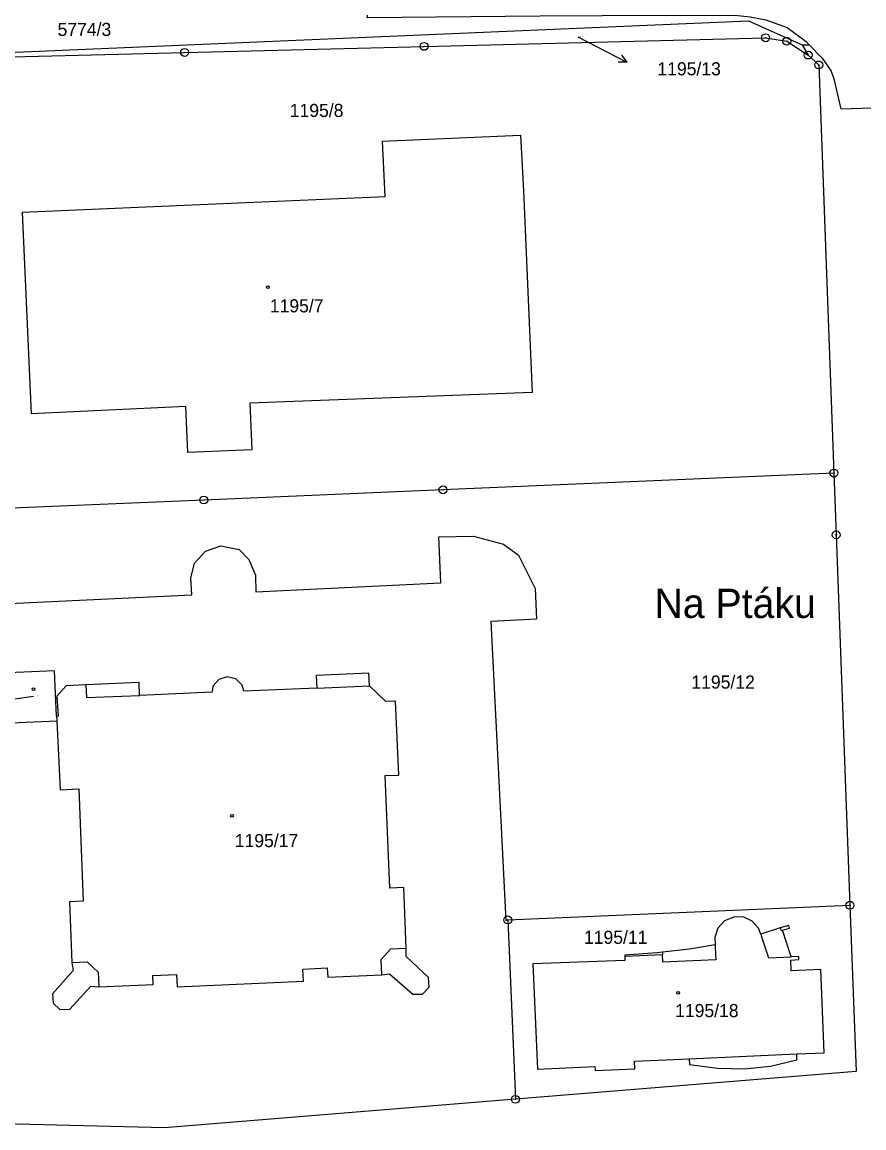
# Model space of a CAD drawing. Extents: x -737240 to -735272, y -1119606 to -1117878.
# Drawn here: x -736473.4 to -736364.4, y -1118998.9 to -1118855.7 of the extents above; entities that cross this region are included whole.
import ezdxf

# ---------------------------------------------------------------- set-up
doc = ezdxf.new("R2010")
doc.units = 0
for name, color, linetype in [('Level 1', 7, 'Continuous'), ('Level 15', 7, 'Continuous'), ('Level 16', 7, 'Continuous'), ('Level 18', 7, 'Continuous'), ('Level 19', 7, 'Continuous'), ('Level 25', 7, 'Continuous'), ('Level 4', 7, 'Continuous')]:
    doc.layers.add(name, color=color, linetype=linetype)

msp = doc.modelspace()

# ---------------------------------------------------------------- linework, layer by layer
at = {"layer": 'Level 1'}
for p, q in [((-736372.4, -1118858.66), (-736371.62, -1118860)), ((-736372.4, -1118858.66), (-736371.48, -1118858.67)), ((-736468.94, -1118945.6), (-736468.91, -1118946.19)), ((-736410.51, -1118971.99), (-736366.21, -1118970.09)), ((-736410.51, -1118971.99), (-736409.52, -1118995.22)), ((-736375.22, -1118973.03), (-736377.76, -1118973.84)), ((-736373.83, -1118976.76), (-736374.95, -1118973.32))]:
    msp.add_line(p, q, dxfattribs=at)
for points in [[(-736428.37, -1118853.26), (-736428.76, -1118855.15), (-736406.31, -1118854.93), (-736390.28, -1118854.83), (-736381.14, -1118854.83), (-736379.11, -1118855.04), (-736377.1, -1118855.44), (-736374.33, -1118856.44), (-736371.88, -1118858.26), (-736371.48, -1118858.67)], [(-736501.58, -1118860.78), (-736379.33, -1118855.55), (-736372.4, -1118858.66)], [(-736483.34, -1118860.44), (-736452.35, -1118859.66), (-736421.35, -1118858.88), (-736377.12, -1118857.76), (-736374.39, -1118858.2), (-736371.62, -1118860)], [(-736371.48, -1118858.67), (-736369.78, -1118860.4), (-736368.64, -1118862.08), (-736368.28, -1118863.06), (-736367.4, -1118866.97), (-736362.05, -1118866.78)], [(-736371.62, -1118860), (-736370.24, -1118861.28), (-736368.28, -1118914.13)], [(-736408.48, -1118877.58), (-736407.34, -1118903.68), (-736443.89, -1118905.09), (-736443.66, -1118911.11), (-736451.92, -1118911.45), (-736452.21, -1118905.49), (-736472.18, -1118906.46), (-736473.34, -1118880.33), (-736426.37, -1118878.32), (-736426.74, -1118871.15), (-736408.87, -1118870.39), (-736408.48, -1118877.58)], [(-736368.28, -1118914.13), (-736418.9, -1118916.3), (-736449.87, -1118917.62), (-736480.84, -1118918.95)], [(-736368.28, -1118914.13), (-736367.99, -1118922.13), (-736366.21, -1118970.09)], [(-736477.79, -1118931.14), (-736451.44, -1118929.89), (-736451.57, -1118927.72), (-736451.08, -1118925.8), (-736449.65, -1118924.23), (-736447.65, -1118923.56), (-736445.3, -1118924.04), (-736444.02, -1118925.33), (-736443.19, -1118927.35), (-736443.13, -1118929.51), (-736419.18, -1118928.35), (-736419.44, -1118922.39), (-736414.95, -1118922.31), (-736411.07, -1118923.33), (-736409.14, -1118924.78), (-736406.97, -1118929.07), (-736406.77, -1118933.06), (-736412.71, -1118933.36), (-736410.76, -1118972.06), (-736410.51, -1118971.99)], [(-736468.94, -1118945.6), (-736469.2, -1118939.73), (-736475.14, -1118939.98), (-736474.84, -1118946.46), (-736468.91, -1118946.19)], [(-736435.24, -1118941.96), (-736444.7, -1118942.35), (-736444.9, -1118941.61), (-736445.72, -1118940.78), (-736446.85, -1118940.5), (-736447.94, -1118940.84), (-736448.7, -1118941.72), (-736448.78, -1118942.52), (-736458.18, -1118942.91)], [(-736428.42, -1118941.68), (-736428.5, -1118940.04), (-736435.31, -1118940.32), (-736435.24, -1118941.96)], [(-736465.14, -1118941.56), (-736467.68, -1118941.7), (-736468.92, -1118943), (-736468.75, -1118945.59), (-736468.94, -1118945.6)], [(-736458.18, -1118942.91), (-736458.25, -1118941.26), (-736465.14, -1118941.56)], [(-736423.65, -1118975.66), (-736423.98, -1118967.79), (-736425.77, -1118967.86), (-736426.4, -1118953.31), (-736424.61, -1118953.23), (-736425.03, -1118943.66), (-736426.3, -1118943.71), (-736428.42, -1118941.68)], [(-736468.91, -1118946.19), (-736468.46, -1118955.14), (-736466.06, -1118955.02), (-736465.5, -1118969.56), (-736467.27, -1118969.64), (-736466.94, -1118977.51)], [(-736366.21, -1118970.09), (-736365.41, -1118991.64), (-736409.52, -1118995.22)], [(-736377.76, -1118973.84), (-736378.04, -1118973.04), (-736378.85, -1118972.15), (-736379.93, -1118971.64), (-736381.12, -1118971.57), (-736382.44, -1118972.09), (-736383.3, -1118973.05), (-736383.69, -1118974.27), (-736383.66, -1118975.2)], [(-736374.95, -1118973.32), (-736374.04, -1118973.04), (-736374.13, -1118972.72), (-736375.22, -1118973.03)], [(-736383.66, -1118975.2), (-736387, -1118975.76), (-736390.49, -1118976.17)], [(-736426.82, -1118979.1), (-736425.82, -1118978.96), (-736422.81, -1118981.62), (-736421.54, -1118981.59), (-736420.71, -1118980.7), (-736420.76, -1118979.43), (-736423.67, -1118976.72), (-736423.65, -1118975.66)], [(-736395.36, -1118976.68), (-736395.34, -1118977.23), (-736407.26, -1118977.68), (-736406.68, -1118991.31), (-736399.22, -1118990.99), (-736399.2, -1118991.49), (-736394.07, -1118991.27), (-736394.11, -1118990.27), (-736387.02, -1118989.96)], [(-736390.49, -1118976.17), (-736391.16, -1118976.25), (-736395.36, -1118976.54), (-736395.36, -1118976.68)], [(-736373.1, -1118989.35), (-736369.53, -1118989.19), (-736369.99, -1118978.4), (-736373.8, -1118978.57), (-736373.86, -1118977.21), (-736372.82, -1118977.13), (-736372.83, -1118976.72), (-736373.83, -1118976.76)], [(-736466.94, -1118977.51), (-736466.77, -1118978.52), (-736469.46, -1118981.55), (-736469.38, -1118982.79), (-736468.53, -1118983.61), (-736467.22, -1118983.55), (-736464.52, -1118980.57), (-736463.47, -1118980.67)], [(-736463.47, -1118980.67), (-736456.43, -1118980.37), (-736456.48, -1118979.18), (-736453.39, -1118979.07), (-736453.31, -1118980.66), (-736436.96, -1118979.93), (-736437.03, -1118978.35), (-736433.88, -1118978.2), (-736433.83, -1118979.4), (-736426.82, -1118979.1)], [(-736387.02, -1118989.96), (-736386.98, -1118990.71), (-736383.37, -1118991.2), (-736379.92, -1118991.29), (-736376.48, -1118990.92), (-736373.07, -1118990.1), (-736373.1, -1118989.35)], [(-736409.52, -1118995.22), (-736454.98, -1118998.92), (-736479.39, -1118998.3)]]:
    msp.add_lwpolyline(points, dxfattribs=at)
at = {"layer": 'Level 16'}
for points in [[(-736401.44, -1118857.64), (-736397.77, -1118859.55), (-736395.108, -1118860.934)], [(-736395.765, -1118860.029), (-736395.108, -1118860.934), (-736396.226, -1118860.916)], [(-736471.93, -1118943.04), (-736474.66, -1118943.45), (-736477.627, -1118943.892)]]:
    msp.add_lwpolyline(points, dxfattribs=at)
at = {"layer": 'Level 25'}
for centre, major_axis in [((-736377.12, -1118857.76), (0.516, 0)), ((-736377.12, -1118857.76), (0.0375, 0)), ((-736374.39, -1118858.2), (0.516, 0)), ((-736452.35, -1118859.66), (0.516, 0)), ((-736421.35, -1118858.88), (0.516, 0)), ((-736421.35, -1118858.88), (0.0375, 0)), ((-736374.39, -1118858.2), (0.0375, 0)), ((-736371.62, -1118860), (0.516, 0)), ((-736452.35, -1118859.66), (0.0375, 0)), ((-736371.62, -1118860), (0.0375, 0)), ((-736370.24, -1118861.28), (0.516, 0)), ((-736370.24, -1118861.28), (0.0375, 0)), ((-736441.57, -1118890.07), (0.18, 0)), ((-736368.28, -1118914.13), (0.516, 0)), ((-736368.28, -1118914.13), (0.0375, 0)), ((-736418.9, -1118916.3), (0.516, 0)), ((-736418.9, -1118916.3), (0.0375, 0)), ((-736449.87, -1118917.62), (0.516, 0)), ((-736449.87, -1118917.62), (0.0375, 0)), ((-736367.99, -1118922.13), (0.516, 0)), ((-736367.99, -1118922.13), (0.0375, 0)), ((-736471.93, -1118942.11), (0.18, 0)), ((-736446.22, -1118958.52), (0.18, 0)), ((-736366.21, -1118970.09), (0.516, 0)), ((-736366.21, -1118970.09), (0.0375, 0)), ((-736410.51, -1118971.99), (0.516, 0)), ((-736410.51, -1118971.99), (0.0375, 0)), ((-736388.45, -1118981.42), (0.18, 0)), ((-736409.52, -1118995.22), (0.516, 0)), ((-736409.52, -1118995.22), (0.0375, 0))]:
    msp.add_ellipse(centre, major_axis=major_axis, ratio=0.9848078, dxfattribs=at)
at = {"layer": 'Level 4'}
for p, q in [((-736435.24, -1118941.96), (-736428.42, -1118941.68)), ((-736395.36, -1118976.68), (-736390.48, -1118976.47)), ((-736390.49, -1118976.17), (-736390.48, -1118976.47)), ((-736387.02, -1118989.96), (-736373.1, -1118989.35))]:
    msp.add_line(p, q, dxfattribs=at)
for points in [[(-736465.14, -1118941.56), (-736465.07, -1118943.2), (-736458.18, -1118942.91)], [(-736377.76, -1118973.84), (-736377.6, -1118974.29), (-736376.75, -1118976.88), (-736373.83, -1118976.76)], [(-736375.22, -1118973.03), (-736375.13, -1118973.38), (-736374.95, -1118973.32)], [(-736383.66, -1118975.2), (-736383.65, -1118975.56), (-736383.56, -1118977.14), (-736390.45, -1118977.47), (-736390.48, -1118976.47)], [(-736426.82, -1118979.1), (-736426.9, -1118977.11), (-736425.67, -1118975.75), (-736423.65, -1118975.66)], [(-736466.94, -1118977.51), (-736464.99, -1118977.43), (-736463.55, -1118978.75), (-736463.47, -1118980.67)]]:
    msp.add_lwpolyline(points, dxfattribs=at)

# ---------------------------------------------------------------- texts
at = {"layer": 'Level 15'}
msp.add_text('Na Ptáku', height=3.8, dxfattribs=at).set_placement((-736391.52, -1118932.9))
at = {"layer": 'Level 16'}
msp.add_text('1195/13', height=1.7, dxfattribs=at).set_placement((-736391.135, -1118862.63))
at = {"layer": 'Level 18'}
for s, height, p in [('5774/3', 1.7, (-736468.81, -1118857.53)), ('1195/13', 0.1, (-736401.265, -1118857.64)), ('1195/8', 1.7, (-736438.74, -1118868.02)), ('1195/12', 1.7, (-736386.735, -1118942.04)), ('1195/11', 1.7, (-736400.645, -1118975.09))]:
    msp.add_text(s, height=height, dxfattribs=at).set_placement(p)
at = {"layer": 'Level 19'}
for s, height, p in [('1195/7', 1.7, (-736441.32, -1118893.32)), ('1195/14', 0.1, (-736471.73, -1118943.04)), ('1195/17', 1.7, (-736445.86, -1118962.57)), ('1195/18', 1.7, (-736388.84, -1118984.58))]:
    msp.add_text(s, height=height, dxfattribs=at).set_placement(p)

doc.saveas('drawing.dxf')
